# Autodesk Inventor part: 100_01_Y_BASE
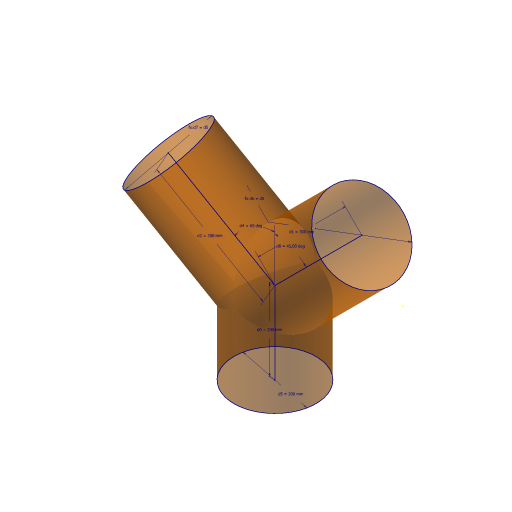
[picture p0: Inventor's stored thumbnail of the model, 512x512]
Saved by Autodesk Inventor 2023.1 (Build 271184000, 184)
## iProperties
Company: Fabian Stasiak CAD Consulting
Category: Autodesk® Inventor® Tutorial Series
Created: 2011-01
Part Number: 100_01_Y_BASE
Document SubType Name: Modeling
Designer: F.Stasiak
Density: 1 g/cm^3
Material: Ogólny
Appearance: Domyślna
Catalog Web Link: www.expertbooks.eu
Author: F.Stasiak
Subject: Sheet Metal Design. Basic and Advanced techniques
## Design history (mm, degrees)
sketch "ANGLES AND PIPES LENGTH"
  geometry: L1 (0, 0)-(0, 200); L2 (0, 200)-(212.132, 412.132); L3 (0, 200)-(-259.808, 350)
  constraints: 6 end point, 1 vertical
  dimensions: "d0" = 200 distance of L1.start L1.end; "d1" = 300 distance of L1.end L2.end; "d2" = 300 distance of L1.end L3.end; "d4" = 60 deg angle of L1 L3; "d8" = 45 deg angle of L1 L2
sketch "PIPE1 DIA = d5"
  geometry: C1 r 100 at (0, 0); 1 further point
  constraints: 1 centre point, 1 coincident
  dimensions: "d5" = 200 diameter of C1
node "Płaszczyzna konstrukcyjna1"
sketch "PIPE2 DIA = d5"
  geometry: C1 r 100 at (0, 0); 2 further points
  constraints: 1 centre point, 1 coincident
  dimensions: "d6" = 200 diameter of C1 (= d5)
node "Płaszczyzna konstrukcyjna2"
sketch "PIPE3 DIA = d5"
  geometry: C1 r 100 at (0, 0); 2 further points
  constraints: 1 centre point, 1 coincident
  dimensions: "d7" = 200 diameter of C1 (= d5)
feature "PIPE1" dims "d9" = 200 (= d0), "d10" = 0
feature "PIPE2" dims "d13" = 300 (= d1), "d14" = 0
feature "PIPE3" dims "d11" = 300 (= d2), "d12" = 0
feature "Utnij1"
feature "Utnij2"
feature "Utnij3"
feature "Utnij4"
feature "Utnij5"
feature "Utnij6"
body "Srf1"
body "Srf3"
body "Srf2"
